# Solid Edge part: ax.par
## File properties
Author: Ionut
Template: Normal.par
Last saved by: user
Revision: 10
Application: Solid Edge
Density: 0.0000078 kg/mm^3
Accuracy: 0.01
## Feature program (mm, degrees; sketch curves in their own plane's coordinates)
sketch for "unnamed Protrusion 1" plane through (0, 0, 0) normal (1, 0, 0) x-axis (0, 1, 0)
  circle centre (0, 0) radius 4
extrude "unnamed Protrusion 1" add finite 46 along +normal
sketch for "ExtrudedProtrusion_2" plane through (46, 0, 0) normal (1, 0, 0) x-axis (0, 1, 0)
  line (0, 0) -> (0, 0)
  circle centre (0, 0) radius 7
extrude "ExtrudedProtrusion_2" add finite 2 along +normal
sketch for "unnamed Cutout 1" plane through (48, 0, 0) normal (1, 0, 0) x-axis (0, 1, 0)
  circle centre (0, 7) radius 1
extrude "unnamed Cutout 1" cut through along -normal
sketch used by "ExtrudedCutout_2" plane through (0, 0, 0) normal (-1, 0, 0) x-axis (0, 0, 1)
extrude "ExtrudedCutout_2" cut finite 40 along -normal
pattern "unnamed Pattern 1" of "ExtrudedCutout_2"
extrude "unnamed Cutout 2" cut finite 40
extrude "unnamed Cutout 3" cut finite 40
extrude "unnamed Cutout 4" cut finite 40
extrude "unnamed Cutout 5" cut finite 40
extrude "unnamed Cutout 6" cut finite 40
extrude "unnamed Cutout 7" cut finite 40
extrude "unnamed Cutout 8" cut finite 40
sketch for "unnamed RevolvedCutout 1" plane through (0, 0, 0) normal (0, -1, 0) x-axis (1, 0, 0)
  line (-0.0347, 0.0554) -> (8.3584, 4.4054)
revolve "unnamed RevolvedCutout 1" cut full turn 360 deg about sketch line (-5.1472, 0) -> (7.6839, 0)
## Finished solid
Body 1: solid body, 23 faces, 56 edges, 36 vertices.
  Faces by surface: cylinder 11, plane 11, cone 1
  Edges by curve: circle 30, line 18, intersection 8
Bounding box of the edges (mm): 48.000 x 14.000 x 13.929, from (0, -7, -7) to (48, 7, 6.9286).
Cylindrical faces by radius (mm): R1 x9, R4 x1, R7 x1
Conical faces (half-angle, radius in mm at the cone's reference point): 27.3968 deg R0.0554 x1
Planar faces by outward normal: +x 1, -x 10
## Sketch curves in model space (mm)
line (-5.1472, 0, 0) -> (60.5413, 0, 0)
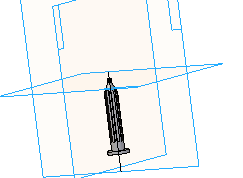
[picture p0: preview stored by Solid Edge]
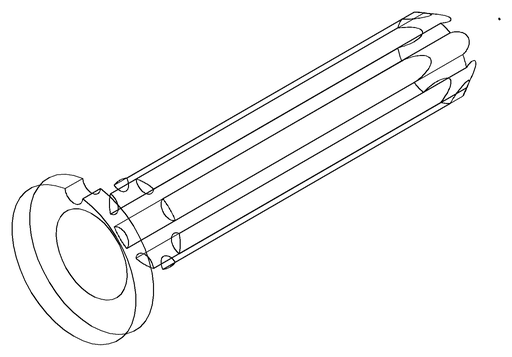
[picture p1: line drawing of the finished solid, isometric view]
